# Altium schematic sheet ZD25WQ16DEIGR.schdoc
size 127 x 101 mm
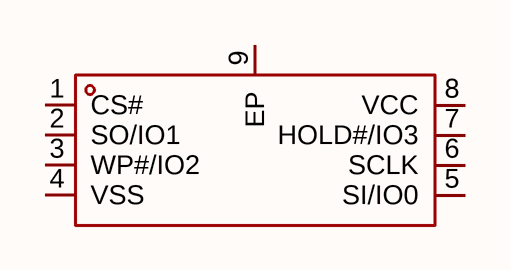
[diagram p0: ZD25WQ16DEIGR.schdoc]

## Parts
U?  zd25wq16deigr  [USON-8_L3.0-W2.0-P0.50-BL-EP1.6_MX25R1635FZUIH0]  (value not drawn)

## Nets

Not connected (* = marked no-connect by the designer): U? 1(CS#) 2(SO/IO1) 3(WP#/IO2) 4(VSS) 5(SI/IO0) 6(SCLK) 7(HOLD#/IO3) 8(VCC) 9(EP)

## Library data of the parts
U? = zd25wq16deigr: 接口类型:SPI;存储容量:16Mbit;时钟频率(fc):104MHz;; Manufacturer: Zetta(澜智); AddInBom: yes; ModelId: 28186e7ba6674336bd66ab9addffff24; ModelTransform: 79.1337,118.8974,0,0,0,0,0,0,0; Interface: SPI; Memory Size: 16Mbit; Clock Frequency: 104MHz; Voltage - Supply: 1.65V~3.6V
